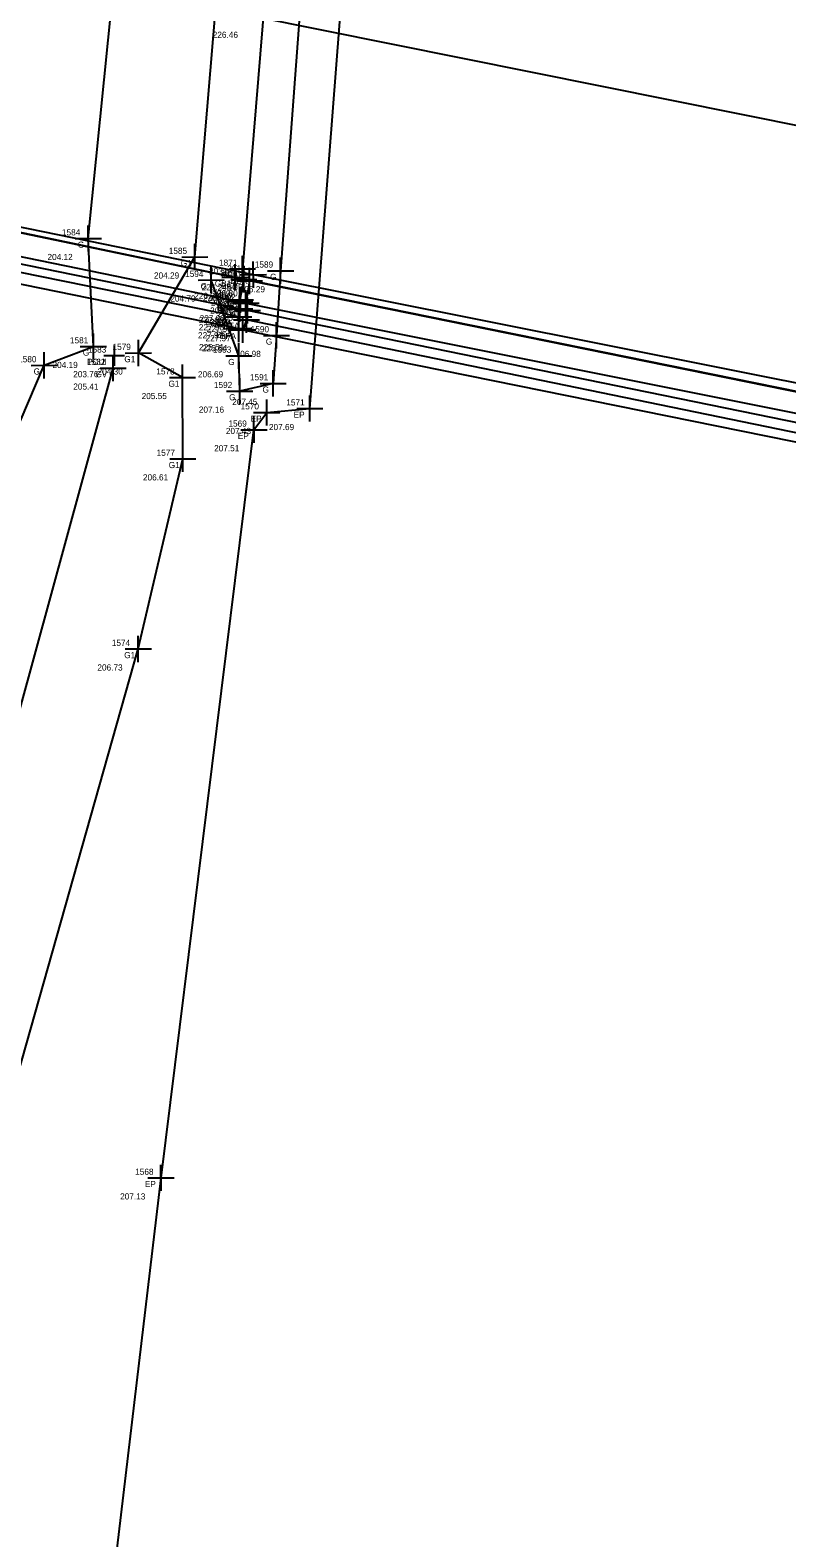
# Model space of a CAD drawing. Extents: x 1158983 to 1160032, y 610902 to 611573.
# Drawn here: x 1159364.2 to 1159401, y 611195 to 611268.4 of the extents above; entities that cross this region are included whole.
import ezdxf

# ---------------------------------------------------------------- set-up
doc = ezdxf.new("R2010")
doc.units = 0
for name, color, linetype in [('Default', 7, 'Continuous'), ('S_Bridge_Centerline', 7, 'Continuous'), ('S_Bridge_Curb', 7, 'Continuous'), ('S_Bridge_Deck', 7, 'Continuous'), ('S_Bridge_ExpansionJoint', 7, 'Continuous'), ('S_Bridge_Fascia', 7, 'Continuous'), ('S_Drainage_Culvert_Top', 7, 'Continuous'), ('S_Drainage_Invert', 7, 'Continuous'), ('S_Field_Code', 7, 'Continuous'), ('S_Ground_Elevation', 7, 'Continuous'), ('S_Guardrail_Beam', 7, 'Continuous'), ('S_Misc_MiscFeature', 7, 'Continuous'), ('S_Point_Elevation', 7, 'Continuous'), ('S_Point_Name', 7, 'Continuous'), ('S_Roadway_Edge_Pavement', 7, 'Continuous'), ('S_Survey_Shot', 7, 'Continuous')]:
    doc.layers.add(name, color=color, linetype=linetype)

msp = doc.modelspace()

# ---------------------------------------------------------------- linework, layer by layer
at = {"layer": 'Default'}
msp.add_line((1159368.293, 611252.563), (1159368.293, 611252.563), dxfattribs=at)
at = {"layer": 'S_Bridge_Centerline'}
msp.add_lwpolyline([(1159333.27, 611277.49), (1159375.085, 611269.079), (1159432.648, 611257.515), (1159502.769, 611243.159), (1159572.889, 611228.86), (1159630.259, 611216.999), (1159672.294, 611208.379)], dxfattribs=at)
at = {"layer": 'S_Bridge_Curb'}
msp.add_line((1159374.448, 611255.282), (1159374.448, 611255.282), dxfattribs=at)
for points in [[(1159374.407, 611255.197), (1159374.607, 611256.276), (1159332.105, 611265.121), (1159331.814, 611263.947)], [(1159431.968, 611243.66), (1159432.006, 611244.597), (1159374.882, 611256.199), (1159374.713, 611255.117)]]:
    msp.add_lwpolyline(points, close=True, dxfattribs=at)
at = {"layer": 'S_Bridge_Deck'}
msp.add_lwpolyline([(1159333.801, 611289.348), (1159375.965, 611280.699), (1159433.546, 611269.247), (1159503.551, 611254.972), (1159573.652, 611240.691), (1159630.945, 611229.008), (1159674.004, 611220.503), (1159672.341, 611196.28), (1159630.068, 611204.797), (1159572.75, 611216.514), (1159502.493, 611230.859), (1159432.439, 611245.062), (1159375.072, 611256.503), (1159331.888, 611265.329)], close=True, dxfattribs=at)
at = {"layer": 'S_Bridge_ExpansionJoint'}
msp.add_lwpolyline([(1159376.494, 611280.457), (1159374.544, 611256.788)], dxfattribs=at)
at = {"layer": 'S_Bridge_Fascia'}
for points in [[(1159374.365, 611253.879), (1159374.366, 611254.457), (1159331.842, 611263.085), (1159331.733, 611262.58)], [(1159431.641, 611242.253), (1159431.696, 611242.594), (1159374.735, 611254.312), (1159374.563, 611253.824)]]:
    msp.add_lwpolyline(points, close=True, dxfattribs=at)
at = {"layer": 'S_Drainage_Culvert_Top'}
msp.add_lwpolyline([(1159357.648, 611213.251), (1159368.247, 611251.957)], dxfattribs=at)
at = {"layer": 'S_Drainage_Invert'}
for p, q in [((1159367.793, 611252.563), (1159368.793, 611252.563)), ((1159368.293, 611253.063), (1159368.293, 611252.063))]:
    msp.add_line(p, q, dxfattribs=at)
at = {"layer": 'S_Ground_Elevation'}
for points in [[(1159355.399, 611212.784), (1159354.868, 611217.296), (1159362.619, 611238.747), (1159363.344, 611248.476), (1159364.893, 611252.092), (1159367.286, 611253.012), (1159367.04, 611258.265), (1159369.176, 611279.512)], [(1159359.22, 611211.166), (1159362.779, 611214.646), (1159369.471, 611238.288), (1159371.639, 611247.54), (1159371.624, 611251.498), (1159369.477, 611252.693), (1159372.225, 611257.365), (1159373.898, 611277.257)], [(1159377.86, 611276.248), (1159376.4, 611256.698), (1159376.196, 611253.55), (1159376.033, 611251.213), (1159374.408, 611250.837), (1159374.364, 611252.556), (1159373.021, 611256.244)]]:
    msp.add_lwpolyline(points, dxfattribs=at)
at = {"layer": 'S_Guardrail_Beam'}
msp.add_lwpolyline([(1159962.355, 611128.723), (1159954.927, 611131.331), (1159940.804, 611136.335), (1159922.846, 611140.981), (1159878.137, 611150.269), (1159824.181, 611161.329), (1159771.192, 611171.967), (1159724.558, 611182.82), (1159696.585, 611190.71), (1159683.564, 611193.82), (1159671.877, 611196.264), (1159629.625, 611204.61), (1159571.633, 611216.492), (1159501.577, 611230.682), (1159431.638, 611244.705), (1159374.182, 611256.374), (1159332.105, 611265.121)], dxfattribs=at)
at = {"layer": 'S_Misc_MiscFeature'}
for points in [[(1159374.405, 611254.846), (1159331.92, 611263.519)], [(1159431.791, 611243.111), (1159374.79, 611254.764)]]:
    msp.add_lwpolyline(points, dxfattribs=at)
at = {"layer": 'S_Roadway_Edge_Pavement'}
msp.add_lwpolyline([(1159304.573, 610945.043), (1159314.096, 610964.406), (1159323.633, 610989.35), (1159331.421, 611011.653), (1159338.354, 611034.073), (1159347.364, 611068.541), (1159355.808, 611107.893), (1159362.207, 611145.629), (1159367.03, 611182.611), (1159370.578, 611212.546), (1159375.102, 611248.958), (1159375.723, 611249.798), (1159377.82, 611249.989), (1159380.874, 611289.348), (1159380.688, 611291.325)], dxfattribs=at)
at = {"layer": 'S_Survey_Shot'}
for p, q in [((1159367.042, 611257.629), (1159367.039, 611258.901)), ((1159366.404, 611258.264), (1159367.677, 611258.267)), ((1159367.04, 611258.265), (1159367.04, 611258.265)), ((1159372.226, 611256.729), (1159372.224, 611258.002)), ((1159371.589, 611257.364), (1159372.861, 611257.367)), ((1159372.225, 611257.365), (1159372.225, 611257.365)), ((1159373.023, 611255.608), (1159373.02, 611256.881)), ((1159374.184, 611255.738), (1159374.181, 611257.011)), ((1159374.546, 611256.152), (1159374.543, 611257.425)), ((1159374.608, 611255.64), (1159374.605, 611256.912)), ((1159374.883, 611255.562), (1159374.88, 611256.835)), ((1159375.073, 611255.867), (1159375.07, 611257.14)), ((1159376.401, 611256.062), (1159376.399, 611257.334)), ((1159372.385, 611256.243), (1159373.658, 611256.246)), ((1159373.021, 611256.244), (1159373.021, 611256.244)), ((1159373.546, 611256.373), (1159374.819, 611256.376)), ((1159373.908, 611256.787), (1159375.181, 611256.79)), ((1159373.971, 611256.275), (1159375.243, 611256.277)), ((1159374.182, 611256.374), (1159374.182, 611256.374)), ((1159374.246, 611256.197), (1159375.518, 611256.2)), ((1159374.436, 611256.502), (1159375.708, 611256.505)), ((1159374.544, 611256.788), (1159374.544, 611256.788)), ((1159374.607, 611256.276), (1159374.607, 611256.276)), ((1159374.882, 611256.199), (1159374.882, 611256.199)), ((1159375.072, 611256.503), (1159375.072, 611256.503)), ((1159375.764, 611256.696), (1159377.036, 611256.699)), ((1159376.4, 611256.698), (1159376.4, 611256.698)), ((1159374.406, 611254.21), (1159374.404, 611255.483)), ((1159374.408, 611254.561), (1159374.406, 611255.833)), ((1159374.449, 611254.646), (1159374.447, 611255.919)), ((1159374.714, 611254.48), (1159374.712, 611255.753)), ((1159374.792, 611254.128), (1159374.789, 611255.4)), ((1159373.769, 611254.845), (1159375.041, 611254.848)), ((1159373.771, 611255.196), (1159375.043, 611255.198)), ((1159373.812, 611255.281), (1159375.084, 611255.284)), ((1159374.077, 611255.115), (1159375.349, 611255.118)), ((1159374.154, 611254.763), (1159375.426, 611254.765)), ((1159374.367, 611253.821), (1159374.365, 611255.094)), ((1159374.405, 611254.846), (1159374.405, 611254.846)), ((1159374.407, 611255.197), (1159374.407, 611255.197)), ((1159374.448, 611255.282), (1159374.448, 611255.282)), ((1159374.713, 611255.117), (1159374.713, 611255.117)), ((1159374.737, 611253.675), (1159374.734, 611254.948)), ((1159374.79, 611254.764), (1159374.79, 611254.764)), ((1159373.729, 611253.878), (1159375.001, 611253.881)), ((1159373.73, 611254.456), (1159375.002, 611254.459)), ((1159374.099, 611254.31), (1159375.371, 611254.313)), ((1159374.366, 611253.243), (1159374.364, 611254.515)), ((1159374.365, 611253.879), (1159374.365, 611253.879)), ((1159374.366, 611254.457), (1159374.366, 611254.457)), ((1159374.565, 611253.187), (1159374.562, 611254.46)), ((1159374.735, 611254.312), (1159374.735, 611254.312)), ((1159376.197, 611252.913), (1159376.195, 611254.186)), ((1159367.287, 611252.376), (1159367.284, 611253.648)), ((1159369.478, 611252.057), (1159369.476, 611253.33)), ((1159373.927, 611253.822), (1159375.2, 611253.825)), ((1159374.365, 611251.92), (1159374.363, 611253.193)), ((1159374.563, 611253.824), (1159374.563, 611253.824)), ((1159375.56, 611253.548), (1159376.832, 611253.551)), ((1159376.196, 611253.55), (1159376.196, 611253.55)), ((1159364.894, 611251.456), (1159364.891, 611252.728)), ((1159366.649, 611253.011), (1159367.922, 611253.014)), ((1159367.286, 611253.012), (1159367.286, 611253.012)), ((1159368.248, 611251.321), (1159368.245, 611252.593)), ((1159368.841, 611252.692), (1159370.113, 611252.695)), ((1159369.477, 611252.693), (1159369.477, 611252.693)), ((1159373.728, 611252.555), (1159375, 611252.558)), ((1159374.364, 611252.556), (1159374.364, 611252.556)), ((1159364.257, 611252.091), (1159365.529, 611252.093)), ((1159364.893, 611252.092), (1159364.893, 611252.092)), ((1159367.61, 611251.955), (1159368.883, 611251.958)), ((1159368.247, 611251.957), (1159368.247, 611251.957)), ((1159371.625, 611250.862), (1159371.622, 611252.135)), ((1159376.034, 611250.576), (1159376.032, 611251.849)), ((1159370.987, 611251.497), (1159372.26, 611251.5)), ((1159371.624, 611251.498), (1159371.624, 611251.498)), ((1159374.41, 611250.201), (1159374.407, 611251.473)), ((1159375.397, 611251.211), (1159376.669, 611251.214)), ((1159376.033, 611251.213), (1159376.033, 611251.213)), ((1159373.772, 611250.836), (1159375.045, 611250.838)), ((1159374.408, 611250.837), (1159374.408, 611250.837)), ((1159375.725, 611249.162), (1159375.722, 611250.434)), ((1159377.821, 611249.353), (1159377.818, 611250.626)), ((1159375.087, 611249.797), (1159376.36, 611249.799)), ((1159375.104, 611248.322), (1159375.101, 611249.594)), ((1159375.723, 611249.798), (1159375.723, 611249.798)), ((1159377.183, 611249.988), (1159378.456, 611249.991)), ((1159377.82, 611249.989), (1159377.82, 611249.989)), ((1159374.466, 611248.957), (1159375.739, 611248.959)), ((1159375.102, 611248.958), (1159375.102, 611248.958)), ((1159371.64, 611246.904), (1159371.637, 611248.176)), ((1159371.003, 611247.539), (1159372.275, 611247.541)), ((1159371.639, 611247.54), (1159371.639, 611247.54)), ((1159369.472, 611237.652), (1159369.469, 611238.925)), ((1159368.834, 611238.287), (1159370.107, 611238.29)), ((1159369.471, 611238.288), (1159369.471, 611238.288)), ((1159370.579, 611211.91), (1159370.576, 611213.182)), ((1159369.941, 611212.545), (1159371.214, 611212.547)), ((1159370.578, 611212.546), (1159370.578, 611212.546))]:
    msp.add_line(p, q, dxfattribs=at)

# ---------------------------------------------------------------- texts
at = {"layer": 'S_Field_Code'}
for s, p in [('G', (1159366.526, 611257.815)), ('G1', (1159371.54, 611256.915)), ('G', (1159372.506, 611255.794)), ('GB1', (1159373.197, 611255.924)), ('BCB', (1159373.492, 611255.826)), ('BEJ', (1159373.514, 611256.338)), ('BDK', (1159373.971, 611256.053)), ('G', (1159375.885, 611256.248)), ('BCB', (1159373.767, 611255.749)), ('BCB', (1159373.292, 611254.747)), ('BCB', (1159373.333, 611254.832)), ('ZZ', (1159373.604, 611254.396)), ('BCB', (1159373.598, 611254.667)), ('ZZ', (1159373.989, 611254.314)), ('BFA', (1159373.249, 611254.007)), ('BFA', (1159373.618, 611253.862)), ('BFA', (1159373.248, 611253.429)), ('BFA', (1159373.446, 611253.373)), ('G', (1159375.681, 611253.1)), ('G', (1159366.771, 611252.562)), ('PCUI', (1159366.98, 611252.113)), ('G1', (1159368.792, 611252.243)), ('G', (1159373.849, 611252.106)), ('G', (1159364.378, 611251.642)), ('CV', (1159367.403, 611251.507)), ('G1', (1159370.939, 611251.048)), ('G', (1159375.518, 611250.763)), ('G', (1159373.893, 611250.387)), ('EP', (1159374.937, 611249.348)), ('EP', (1159377.033, 611249.539)), ('EP', (1159374.316, 611248.508)), ('G1', (1159370.954, 611247.09)), ('G1', (1159368.786, 611237.838)), ('EP', (1159369.791, 611212.096))]:
    msp.add_text(s, height=0.3, dxfattribs=at).set_placement(p)
at = {"layer": 'S_Point_Elevation'}
for s, p in [('226.46', (1159373.096, 611268.029)), ('204.12', (1159365.052, 611257.215)), ('204.29', (1159370.236, 611256.315)), ('204.79', (1159371.032, 611255.194)), ('226.93', (1159372.193, 611255.324)), ('226.24', (1159372.555, 611255.738)), ('226.94', (1159372.618, 611255.226)), ('226.92', (1159372.893, 611255.149)), ('226.30', (1159373.083, 611255.453)), ('205.29', (1159374.411, 611255.648)), ('227.98', (1159372.416, 611253.796)), ('227.00', (1159372.418, 611254.147)), ('227.00', (1159372.459, 611254.232)), ('227.00', (1159372.724, 611254.067)), ('227.98', (1159372.801, 611253.714)), ('227.97', (1159372.377, 611253.407)), ('227.97', (1159372.746, 611253.262)), ('225.51', (1159372.426, 611252.829)), ('225.54', (1159372.574, 611252.774)), ('206.98', (1159374.207, 611252.5)), ('204.19', (1159365.297, 611251.962)), ('203.76', (1159366.304, 611251.513)), ('204.30', (1159367.488, 611251.643)), ('206.69', (1159372.375, 611251.506)), ('205.41', (1159366.307, 611250.907)), ('205.55', (1159369.635, 611250.448)), ('207.45', (1159374.044, 611250.163)), ('207.16', (1159372.419, 611249.787)), ('207.43', (1159373.734, 611248.748)), ('207.69', (1159375.831, 611248.939)), ('207.51', (1159373.163, 611247.908)), ('206.61', (1159369.699, 611246.49)), ('206.73', (1159367.482, 611237.238)), ('207.13', (1159368.589, 611211.496))]:
    msp.add_text(s, height=0.3, dxfattribs=at).set_placement(p)
at = {"layer": 'S_Point_Name'}
for s, p in [('1584', (1159365.756, 611258.415)), ('1585', (1159370.954, 611257.515)), ('2031', (1159372.914, 611256.524)), ('1871', (1159373.401, 611256.938)), ('2012', (1159373.803, 611256.653)), ('1589', (1159375.143, 611256.848)), ('1594', (1159371.751, 611256.394)), ('2011', (1159373.468, 611256.426)), ('2001', (1159373.616, 611256.349)), ('2009', (1159373.066, 611255.432)), ('2010', (1159373.141, 611255.347)), ('2002', (1159373.317, 611255.267)), ('2007', (1159372.968, 611254.607)), ('2008', (1159373.009, 611254.996)), ('2004', (1159373.325, 611254.462)), ('2003', (1159373.394, 611254.914)), ('2006', (1159372.983, 611254.029)), ('2005', (1159373.167, 611253.974)), ('1590', (1159374.942, 611253.7)), ('1581', (1159366.145, 611253.162)), ('1579', (1159368.218, 611252.843)), ('1580', (1159363.624, 611252.242)), ('1582', (1159366.976, 611252.107)), ('1583', (1159367.022, 611252.713)), ('1593', (1159373.107, 611252.706)), ('1578', (1159370.351, 611251.648)), ('1592', (1159373.152, 611250.987)), ('1591', (1159374.906, 611251.363)), ('1570', (1159374.453, 611249.948)), ('1571', (1159376.676, 611250.139)), ('1569', (1159373.86, 611249.108)), ('1577', (1159370.363, 611247.69)), ('1574', (1159368.183, 611238.438)), ('1568', (1159369.321, 611212.696))]:
    msp.add_text(s, height=0.3, dxfattribs=at).set_placement(p)

doc.saveas('drawing.dxf')
